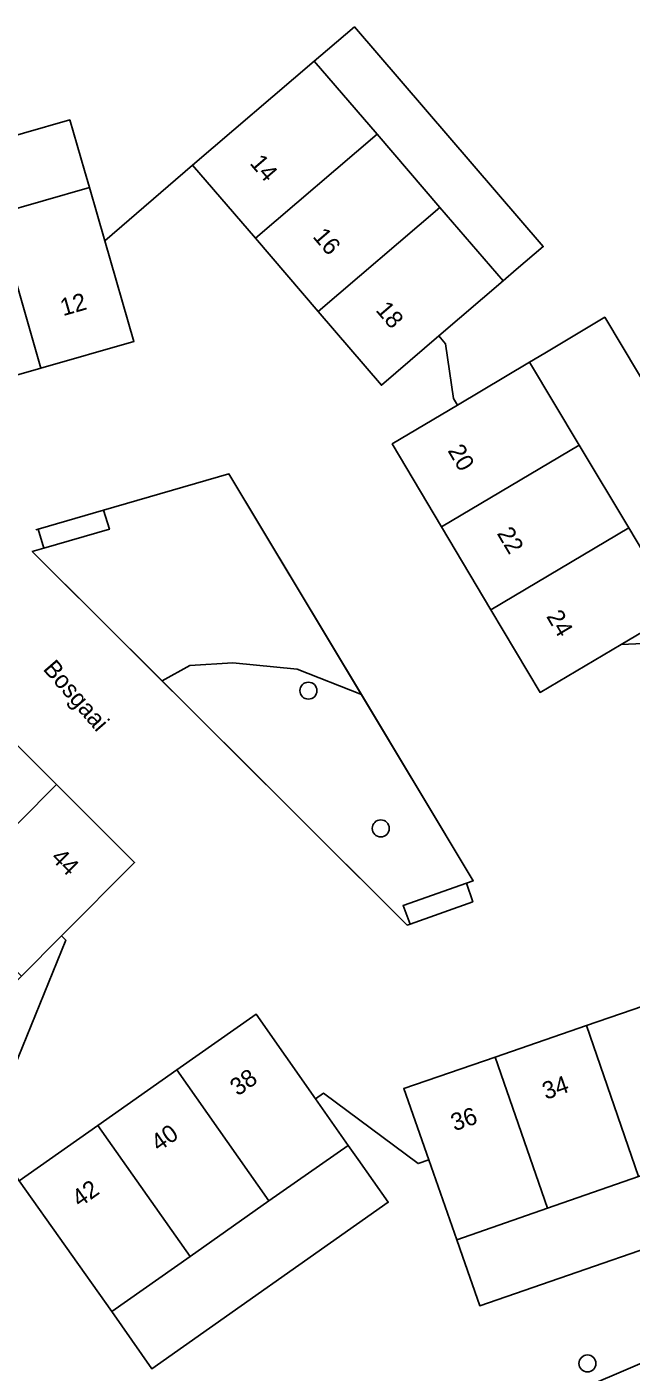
# Model space of a CAD drawing. Extents: x 156661 to 157576, y 383570 to 384425.
# Drawn here: x 156981.6 to 157016.4, y 384130.7 to 384208 of the extents above; entities that cross this region are included whole.
import ezdxf

# ---------------------------------------------------------------- set-up
doc = ezdxf.new("R2010")
doc.units = 0
for name, color, linetype in [('IMGEO_Boom', 7, 'Continuous'), ('IMGEO_Erf', 7, 'Continuous'), ('IMGEO_Grasland_overig', 7, 'Continuous'), ('IMGEO_Greppel_droge_sloot', 7, 'Continuous'), ('IMGEO_Groenvoorziening', 7, 'Continuous'), ('IMGEO_Hek', 7, 'Continuous'), ('IMGEO_Muur', 7, 'Continuous'), ('IMGEO_Openbare_ruimte_label', 7, 'Continuous'), ('IMGEO_Pand', 7, 'Continuous'), ('IMGEO_Pand_nummerreeks', 7, 'Continuous')]:
    doc.layers.add(name, color=color, linetype=linetype)

msp = doc.modelspace()

# ---------------------------------------------------------------- linework, layer by layer
at = {"layer": 'IMGEO_Boom'}
for centre in [(156997.796, 384169.879), (157001.957, 384161.96), (157013.847, 384131.188)]:
    msp.add_circle(centre, 0.489, dxfattribs=at)
at = {"layer": 'IMGEO_Erf'}
for points in [[(157009.748, 384194.09), (157011.3, 384195.414), (157000.438, 384208.049), (156998.899, 384206.731), (156998.135, 384206.077), (157001.743, 384201.88), (157005.362, 384197.671), (157008.993, 384193.447)], [(156984.917, 384199.793), (156984.074, 384202.696), (156968.071, 384198.098), (156968.921, 384195.187), (156969.2, 384194.233), (156974.52, 384195.759), (156979.855, 384197.288), (156985.199, 384198.821)], [(157010.52, 384188.776), (157013.371, 384184.001), (157016.217, 384179.236), (157019.063, 384174.471), (157019.935, 384174.982), (157023.406, 384177.017), (157014.839, 384191.348), (157011.387, 384189.293)], [(156989.379, 384170.448), (156981.917, 384177.878), (156982.578, 384178.07), (156982.259, 384179.174), (156986.004, 384180.266), (156993.221, 384182.345), (157000.843, 384169.66), (157007.279, 384158.95), (157006.888, 384158.811), (157007.248, 384157.736), (157003.64, 384156.445), (157003.485, 384156.403)], [(156987.061, 384133.355), (156988.79, 384130.883), (157002.388, 384140.459), (157000.656, 384142.92), (157000.083, 384143.732), (156995.529, 384140.532), (156990.988, 384137.34), (156986.487, 384134.177)], [(157006.661, 384137.356), (157007.655, 384134.505), (157023.4, 384139.952), (157022.393, 384142.815), (157022.058, 384143.767), (157016.781, 384141.934), (157011.538, 384140.114), (157006.33, 384138.305)]]:
    msp.add_lwpolyline(points, close=True, dxfattribs=at)
for points in [[(157027.182, 384173.059), (157015.79, 384172.535), (157011.124, 384169.776), (157008.291, 384174.536), (157005.452, 384179.305), (157002.615, 384184.072), (157006.364, 384186.303), (157006.142, 384186.685), (157005.679, 384189.83), (157005.303, 384190.28), (157001.995, 384187.441), (156998.36, 384191.681), (156994.747, 384195.895), (156991.136, 384200.107), (156986.086, 384195.753), (156987.761, 384189.959), (156982.403, 384188.422), (156977.068, 384186.892)], [(156979.369, 384168.397), (156983.3, 384164.478), (156987.799, 384159.993), (156983.601, 384155.776), (156983.841, 384155.53), (156979.346, 384144.483)], [(156981.162, 384141.701), (156985.686, 384144.882), (156990.226, 384148.075), (156994.79, 384151.285), (156998.209, 384146.407), (156998.668, 384146.731), (157004.101, 384142.683), (157004.719, 384142.893), (157003.277, 384147.001), (157008.542, 384148.812), (157013.79, 384150.618), (157019.05, 384152.427)]]:
    msp.add_lwpolyline(points, dxfattribs=at)
at = {"layer": 'IMGEO_Grasland_overig'}
for points in [[(156993.221, 384182.345), (156986.004, 384180.266), (156986.349, 384179.165), (156982.578, 384178.07), (156981.917, 384177.878), (156989.379, 384170.448), (156990.983, 384171.325), (156993.451, 384171.47), (156997.153, 384171.107), (157000.843, 384169.66)], [(156982.578, 384178.07), (156986.349, 384179.165), (156986.004, 384180.266), (156982.259, 384179.174)], [(157000.843, 384169.66), (156997.153, 384171.107), (156993.451, 384171.47), (156990.983, 384171.325), (156989.379, 384170.448), (157003.485, 384156.403), (157003.64, 384156.445), (157003.242, 384157.518), (157006.888, 384158.811), (157007.279, 384158.95)], [(157006.888, 384158.811), (157003.242, 384157.518), (157003.64, 384156.445), (157007.248, 384157.736)]]:
    msp.add_lwpolyline(points, close=True, dxfattribs=at)
at = {"layer": 'IMGEO_Greppel_droge_sloot'}
msp.add_lwpolyline([(157020.852, 384127.544), (157028.032, 384133.073), (157030.878, 384136.293), (157029.595, 384139.138), (157020.136, 384132.567), (157011.975, 384129.074), (157003.697, 384126.69), (156998.763, 384122.638), (157001.811, 384121.29), (157011.124, 384122.683)], close=True, dxfattribs=at)
at = {"layer": 'IMGEO_Groenvoorziening'}
for points in [[(156968.071, 384198.098), (156984.074, 384202.696), (156984.917, 384199.793), (156985.199, 384198.821), (156986.086, 384195.753), (156991.136, 384200.107), (156998.135, 384206.077), (156998.899, 384206.731), (157000.438, 384208.049), (157011.3, 384195.414), (157009.748, 384194.09), (157008.993, 384193.447), (157005.303, 384190.28), (157005.679, 384189.83), (157006.142, 384186.685), (157006.364, 384186.303), (157010.52, 384188.776), (157011.387, 384189.293), (157014.839, 384191.348), (157023.406, 384177.017)], [(157019.063, 384174.471), (157015.79, 384172.535), (157027.182, 384173.059)], [(157023.4, 384139.952), (157007.655, 384134.505), (157006.661, 384137.356), (157006.33, 384138.305), (157004.719, 384142.893), (157004.101, 384142.683), (156998.668, 384146.731), (156998.209, 384146.407), (157000.083, 384143.732), (157000.656, 384142.92), (157002.388, 384140.459), (156988.79, 384130.883), (156987.061, 384133.355), (156986.487, 384134.177), (156981.162, 384141.701), (156979.346, 384144.483), (156983.841, 384155.53), (156983.601, 384155.776), (156981.295, 384153.461), (156980.584, 384152.741), (156979.171, 384151.311), (156967.386, 384163.072), (156960.044, 384155.717), (156983.009, 384125.143)]]:
    msp.add_lwpolyline(points, dxfattribs=at)
msp.add_lwpolyline([(157029.595, 384139.138), (157030.878, 384136.293), (157028.032, 384133.073), (157020.852, 384127.544), (157011.124, 384122.683), (157001.811, 384121.29), (156998.763, 384122.638), (157003.697, 384126.69), (157011.975, 384129.074), (157020.136, 384132.567)], close=True, dxfattribs=at)
at = {"layer": 'IMGEO_Hek'}
for points in [[(157006.888, 384158.811), (157007.279, 384158.95), (156993.221, 384182.345), (156986.004, 384180.266)], [(156982.259, 384179.174), (156986.004, 384180.266)], [(156986.004, 384180.266), (156986.349, 384179.165), (156982.578, 384178.07)], [(156982.118, 384179.133), (156982.259, 384179.174)], [(156982.578, 384178.07), (156981.917, 384177.878), (157003.485, 384156.403), (157003.64, 384156.445)], [(157003.64, 384156.445), (157003.242, 384157.518), (157006.888, 384158.811)], [(157007.248, 384157.736), (157003.64, 384156.445)]]:
    msp.add_lwpolyline(points, dxfattribs=at)
at = {"layer": 'IMGEO_Muur'}
for points in [[(156998.899, 384206.731), (157000.438, 384208.049), (157011.3, 384195.414), (157009.748, 384194.09)], [(156998.135, 384206.077), (156998.899, 384206.731)], [(156984.917, 384199.793), (156984.074, 384202.696), (156968.071, 384198.098), (156968.921, 384195.187)], [(156985.199, 384198.821), (156984.917, 384199.793)], [(157008.993, 384193.447), (157009.748, 384194.09)], [(157011.387, 384189.293), (157014.839, 384191.348), (157023.406, 384177.017), (157019.935, 384174.982)], [(157010.52, 384188.776), (157011.387, 384189.293)], [(157000.083, 384143.732), (157000.656, 384142.92)], [(156987.061, 384133.355), (156988.79, 384130.883), (157002.388, 384140.459), (157000.656, 384142.92)], [(157022.393, 384142.815), (157023.4, 384139.952), (157007.655, 384134.505), (157006.661, 384137.356)], [(157006.33, 384138.305), (157006.661, 384137.356)], [(156986.487, 384134.177), (156987.061, 384133.355)]]:
    msp.add_lwpolyline(points, dxfattribs=at)
at = {"layer": 'IMGEO_Pand'}
for points in [[(157001.743, 384201.88), (156998.135, 384206.077), (156991.136, 384200.107), (156994.747, 384195.895)], [(157005.362, 384197.671), (157001.743, 384201.88), (156994.747, 384195.895), (156998.36, 384191.681)], [(156982.403, 384188.422), (156987.761, 384189.959), (156986.086, 384195.753), (156985.199, 384198.821), (156979.855, 384197.288)], [(157005.362, 384197.671), (156998.36, 384191.681), (157001.995, 384187.441), (157005.303, 384190.28), (157008.993, 384193.447)], [(156974.52, 384195.759), (156977.068, 384186.892), (156982.403, 384188.422), (156979.855, 384197.288)], [(157013.371, 384184.001), (157010.52, 384188.776), (157006.364, 384186.303), (157002.615, 384184.072), (157005.452, 384179.305)], [(157008.291, 384174.536), (157016.217, 384179.236), (157013.371, 384184.001), (157005.452, 384179.305)], [(157008.291, 384174.536), (157011.124, 384169.776), (157015.79, 384172.535), (157019.063, 384174.471), (157016.217, 384179.236)], [(156979.369, 384168.397), (156972.871, 384161.856), (156976.802, 384157.938), (156983.3, 384164.478)], [(156983.3, 384164.478), (156976.802, 384157.938), (156981.295, 384153.461), (156983.601, 384155.776), (156987.799, 384159.993)], [(157016.781, 384141.934), (157022.058, 384143.767), (157020.999, 384146.817), (157019.05, 384152.427), (157013.79, 384150.618)], [(156995.529, 384140.532), (157000.083, 384143.732), (156998.209, 384146.407), (156994.79, 384151.285), (156990.226, 384148.075)], [(157016.781, 384141.934), (157013.79, 384150.618), (157008.542, 384148.812), (157011.538, 384140.114)], [(157008.542, 384148.812), (157003.277, 384147.001), (157004.719, 384142.893), (157006.33, 384138.305), (157011.538, 384140.114)], [(156995.529, 384140.532), (156990.226, 384148.075), (156985.686, 384144.882), (156990.988, 384137.34)], [(156990.988, 384137.34), (156985.686, 384144.882), (156981.162, 384141.701), (156986.487, 384134.177)]]:
    msp.add_lwpolyline(points, close=True, dxfattribs=at)

# ---------------------------------------------------------------- texts
at = {"layer": 'IMGEO_Openbare_ruimte_label'}
msp.add_text('Bosgaai', height=1, rotation=310.86241, dxfattribs=at).set_placement((156982.489, 384171.105))
at = {"layer": 'IMGEO_Pand_nummerreeks'}
for s, rotation, p in [('14', 310.60775, (156994.382, 384200.192)), ('16', 310.60775, (156998.002, 384195.97)), ('12', 16.00116, (156983.69, 384191.413)), ('18', 310.60775, (157001.623, 384191.746)), ('20', 300.76189, (157005.779, 384183.683)), ('22', 300.76189, (157008.61, 384178.926)), ('24', 300.76189, (157011.45, 384174.155)), ('44', 315.08881, (156982.932, 384160.213)), ('38', 35.11761, (156993.735, 384146.533)), ('34', 18.98185, (157011.451, 384146.344)), ('36', 18.98185, (157006.194, 384144.536)), ('40', 35.11761, (156989.192, 384143.338)), ('42', 35.11761, (156984.642, 384140.138))]:
    msp.add_text(s, height=1, rotation=rotation, dxfattribs=at).set_placement(p)

doc.saveas('drawing.dxf')
